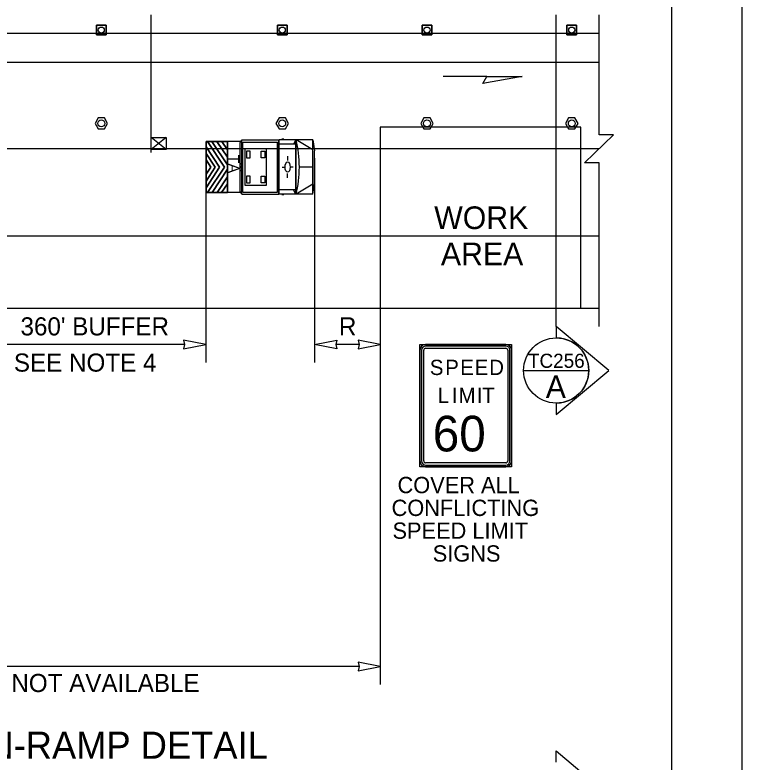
# Model space of a CAD drawing. Extents: x 99999 to 100116, y 99995 to 100013.
# Drawn here: x 100072.847 to 100076.062, y 100004.786 to 100008.087 of the extents above; entities that cross this region are included whole.
import ezdxf

# ---------------------------------------------------------------- set-up
doc = ezdxf.new("R2010")
doc.units = 0
for name, color, linetype in [('RD_MK_LineEdgeYellow', 7, 'Continuous'), ('RD_MK_LineLane', 7, 'Continuous'), ('SH_DE_DetailHeading2Text', 7, 'Continuous'), ('SH_GI_PlotLimits', 7, 'Continuous'), ('SH_GI_SectionCut', 7, 'Continuous'), ('SH_GI_SheetBorder', 7, 'Continuous'), ('TR_SN_ConstructionSigns', 7, 'Continuous'), ('TR_WZ_PortableSignMount5ftMinBlk-Wht', 7, 'Continuous'), ('TR_WZ_TallChanDevice', 7, 'Continuous'), ('TR_WZ_TrafficCone', 7, 'Continuous'), ('TR_WZ_TransportableAttenuator', 7, 'Continuous'), ('TR_WZ_WorkAreaLabel', 7, 'Continuous'), ('TR_WZ_WorkZoneDetails', 7, 'Continuous'), ('TR_WZ_WorkZoneTextCurrent', 7, 'Continuous')]:
    doc.layers.add(name, color=color, linetype=linetype)

msp = doc.modelspace()

# ---------------------------------------------------------------- linework, layer by layer
at = {"layer": 'RD_MK_LineEdgeYellow'}
for p, q in [((100068.195, 100007.8789), (100075.43, 100007.8789)), ((100072.7368, 100007.1109), (100075.43, 100007.1109))]:
    msp.add_line(p, q, dxfattribs=at)
at = {"layer": 'RD_MK_LineLane'}
msp.add_lwpolyline([(100075.43, 100007.4949), (100068.195, 100007.4949)], dxfattribs=at)
at = {"layer": 'SH_GI_PlotLimits'}
msp.add_lwpolyline([(100059.0625, 99999.6875), (100076.0625, 99999.6875), (100076.0625, 100010.6875), (100059.0625, 100010.6875)], close=True, dxfattribs=at)
at = {"layer": 'SH_GI_SectionCut'}
for p, q in [((100075.2407, 100006.7109), (100075.2407, 100008.0869)), ((100075.2407, 100006.7109), (100075.2407, 100006.66)), ((100075.4733, 100006.516), (100075.2407, 100006.7109)), ((100075.2407, 100006.3211), (100075.4733, 100006.516)), ((100075.2407, 100006.372), (100075.2407, 100006.3211)), ((100075.2407, 100004.7848), (100075.2407, 100004.8357)), ((100075.2407, 100004.8357), (100075.4733, 100004.6408))]:
    msp.add_line(p, q, dxfattribs=at)
msp.add_lwpolyline([(100075.0967, 100006.516), (100075.3847, 100006.516)], dxfattribs=at)
msp.add_circle((100075.2407, 100006.516), 0.144, dxfattribs=at)
msp.add_arc((100075.2407, 100006.516), 0.144, 269.9978, 90.0022, dxfattribs=at)
at = {"layer": 'SH_GI_SheetBorder'}
msp.add_line((100075.75, 100010.375), (100075.75, 100000), dxfattribs=at)
at = {"layer": 'TR_SN_ConstructionSigns'}
for p, q in [((100074.6633, 100006.6309), (100075.0177, 100006.6309)), ((100075.0177, 100006.6309), (100074.6633, 100006.6309)), ((100075.0177, 100006.6239), (100074.6633, 100006.6239)), ((100074.6633, 100006.614), (100075.0177, 100006.614)), ((100074.638, 100006.1162), (100074.638, 100006.6056)), ((100074.638, 100006.6056), (100074.638, 100006.1162)), ((100074.6451, 100006.6056), (100074.6451, 100006.1162)), ((100074.6549, 100006.1162), (100074.6549, 100006.6056)), ((100075.0261, 100006.6056), (100075.0261, 100006.1162)), ((100075.036, 100006.1162), (100075.036, 100006.6056)), ((100075.043, 100006.6056), (100075.043, 100006.1162)), ((100075.043, 100006.1162), (100075.043, 100006.6056)), ((100075.0177, 100006.1078), (100074.6633, 100006.1078)), ((100074.6633, 100006.0979), (100075.0177, 100006.0979)), ((100075.0177, 100006.0909), (100074.6633, 100006.0909)), ((100074.6633, 100006.0909), (100075.0177, 100006.0909))]:
    msp.add_line(p, q, dxfattribs=at)
msp.add_lwpolyline([(100074.638, 100006.6309), (100075.043, 100006.6309), (100075.043, 100006.0909), (100074.638, 100006.0909)], close=True, dxfattribs=at)
for centre, radius, start, end in [((100074.6633, 100006.6056), 0.0253, 90, 180), ((100074.6633, 100006.6056), 0.0253, 90, 180), ((100074.6633, 100006.6056), 0.0183, 90, 180), ((100074.6633, 100006.6056), 0.00844, 90, 180), ((100075.0177, 100006.6056), 0.0253, 0, 90), ((100075.0177, 100006.6056), 0.0253, 360, 90), ((100075.0177, 100006.6056), 0.0183, 0, 90), ((100075.0177, 100006.6056), 0.00844, 360, 90), ((100074.6633, 100006.1162), 0.0253, 180, 270), ((100074.6633, 100006.1162), 0.0253, 180, 270), ((100074.6633, 100006.1162), 0.0183, 180, 270), ((100074.6633, 100006.1162), 0.00844, 180, 270), ((100075.0177, 100006.1162), 0.0253, 270, 0), ((100075.0177, 100006.1162), 0.0183, 270, 360), ((100075.0177, 100006.1162), 0.00844, 270, 0), ((100075.0177, 100006.1162), 0.0253, 270, 0)]:
    msp.add_arc(centre, radius, start, end, dxfattribs=at)
at = {"layer": 'TR_WZ_PortableSignMount5ftMinBlk-Wht'}
for p, q in [((100073.45, 100007.4789), (100073.45, 100007.5589)), ((100073.5167, 100007.5449), (100073.45, 100007.4929)), ((100073.5167, 100007.4929), (100073.45, 100007.5449)), ((100073.4834, 100007.5189), (100073.4834, 100007.5189)), ((100073.4835, 100007.519), (100073.4835, 100007.519))]:
    msp.add_line(p, q, dxfattribs=at)
msp.add_lwpolyline([(100073.5167, 100007.5449), (100073.5167, 100007.4929), (100073.45, 100007.4929), (100073.45, 100007.5449)], close=True, dxfattribs=at)
at = {"layer": 'TR_WZ_TallChanDevice'}
for points in [[(100073.2433, 100007.6319), (100073.2155, 100007.6319), (100073.2017, 100007.6079), (100073.2155, 100007.5839), (100073.2433, 100007.5839), (100073.2571, 100007.6079)], [(100074.0433, 100007.6319), (100074.0155, 100007.6319), (100074.0017, 100007.6079), (100074.0155, 100007.5839), (100074.0433, 100007.5839), (100074.0571, 100007.6079)], [(100074.6833, 100007.6319), (100074.6555, 100007.6319), (100074.6417, 100007.6079), (100074.6555, 100007.5839), (100074.6833, 100007.5839), (100074.6971, 100007.6079)], [(100075.3233, 100007.6319), (100075.2955, 100007.6319), (100075.2817, 100007.6079), (100075.2955, 100007.5839), (100075.3233, 100007.5839), (100075.3371, 100007.6079)]]:
    msp.add_lwpolyline(points, close=True, dxfattribs=at)
for points in [[(100073.2433, 100007.6319), (100073.2155, 100007.6319), (100073.2017, 100007.6079), (100073.2155, 100007.5839), (100073.2433, 100007.5839), (100073.2571, 100007.6079), (100073.2433, 100007.6319)], [(100074.0433, 100007.6319), (100074.0155, 100007.6319), (100074.0017, 100007.6079), (100074.0155, 100007.5839), (100074.0433, 100007.5839), (100074.0571, 100007.6079), (100074.0433, 100007.6319)], [(100074.6833, 100007.6319), (100074.6555, 100007.6319), (100074.6417, 100007.6079), (100074.6555, 100007.5839), (100074.6833, 100007.5839), (100074.6971, 100007.6079), (100074.6833, 100007.6319)], [(100075.3233, 100007.6319), (100075.2955, 100007.6319), (100075.2817, 100007.6079), (100075.2955, 100007.5839), (100075.3233, 100007.5839), (100075.3371, 100007.6079), (100075.3233, 100007.6319)]]:
    msp.add_lwpolyline(points, dxfattribs=at)
for centre in [(100073.2294, 100007.6079), (100074.0294, 100007.6079), (100074.6694, 100007.6079), (100075.3094, 100007.6079)]:
    msp.add_circle(centre, 0.015, dxfattribs=at)
at = {"layer": 'TR_WZ_TrafficCone'}
for points in [[(100073.2081, 100008.0416), (100073.2507, 100008.0416), (100073.2507, 100007.9989), (100073.2081, 100007.9989), (100073.2081, 100008.0416)], [(100073.2081, 100007.9989), (100073.2507, 100007.9989), (100073.2507, 100008.0416), (100073.2081, 100008.0416), (100073.2081, 100007.9989)], [(100074.0081, 100008.0416), (100074.0507, 100008.0416), (100074.0507, 100007.9989), (100074.0081, 100007.9989), (100074.0081, 100008.0416)], [(100074.0081, 100007.9989), (100074.0507, 100007.9989), (100074.0507, 100008.0416), (100074.0081, 100008.0416), (100074.0081, 100007.9989)], [(100074.6481, 100008.0416), (100074.6907, 100008.0416), (100074.6907, 100007.9989), (100074.6481, 100007.9989), (100074.6481, 100008.0416)], [(100074.6481, 100007.9989), (100074.6907, 100007.9989), (100074.6907, 100008.0416), (100074.6481, 100008.0416), (100074.6481, 100007.9989)], [(100075.2881, 100008.0416), (100075.3307, 100008.0416), (100075.3307, 100007.9989), (100075.2881, 100007.9989), (100075.2881, 100008.0416)], [(100075.2881, 100007.9989), (100075.3307, 100007.9989), (100075.3307, 100008.0416), (100075.2881, 100008.0416), (100075.2881, 100007.9989)]]:
    msp.add_lwpolyline(points, dxfattribs=at)
for centre in [(100073.2294, 100008.0202), (100074.0294, 100008.0202), (100074.6694, 100008.0202), (100075.3094, 100008.0202)]:
    msp.add_circle(centre, 0.0133, dxfattribs=at)
at = {"layer": 'TR_WZ_TransportableAttenuator'}
for p, q in [((100073.8512, 100007.5349), (100074.0137, 100007.5349)), ((100073.8512, 100007.2949), (100073.8512, 100007.5349)), ((100074.0137, 100007.2949), (100074.0137, 100007.5349)), ((100074.0159, 100007.2949), (100074.0159, 100007.5349)), ((100074.1651, 100007.5349), (100074.0159, 100007.5349)), ((100074.0362, 100007.5383), (100074.0273, 100007.5383)), ((100074.0813, 100007.5163), (100074.0891, 100007.5349)), ((100074.0891, 100007.2949), (100074.0891, 100007.5349)), ((100074.0905, 100007.2949), (100074.0905, 100007.5349)), ((100074.1651, 100007.491), (100074.0905, 100007.5349)), ((100074.1651, 100007.2949), (100074.1651, 100007.5349)), ((100074.1651, 100007.5349), (100074.1724, 100007.4865)), ((100073.7525, 100007.414), (100073.6924, 100007.5046)), ((100073.6924, 100007.5046), (100073.6924, 100007.4751)), ((100073.6924, 100007.4751), (100073.6924, 100007.5046)), ((100073.6924, 100007.5046), (100073.7525, 100007.414)), ((100073.7186, 100007.5275), (100073.6986, 100007.5275)), ((100073.6986, 100007.5275), (100073.7735, 100007.4147)), ((100073.7735, 100007.4147), (100073.6986, 100007.5275)), ((100073.6986, 100007.5275), (100073.7186, 100007.5275)), ((100073.7868, 100007.4248), (100073.7186, 100007.5275)), ((100073.7186, 100007.5275), (100073.7868, 100007.4248)), ((100073.7622, 100007.5275), (100073.7406, 100007.5275)), ((100073.7406, 100007.5275), (100073.7868, 100007.458)), ((100073.7868, 100007.458), (100073.7406, 100007.5275)), ((100073.7406, 100007.5275), (100073.7622, 100007.5275)), ((100073.7868, 100007.4912), (100073.7622, 100007.5275)), ((100073.7622, 100007.5275), (100073.7868, 100007.4912)), ((100073.8512, 100007.5273), (100073.7868, 100007.5273)), ((100073.7868, 100007.5273), (100073.7868, 100007.302)), ((100073.8436, 100007.3062), (100073.8436, 100007.5237)), ((100073.8471, 100007.531), (100073.8506, 100007.531)), ((100073.8506, 100007.2989), (100073.8506, 100007.531)), ((100073.8512, 100007.3024), (100073.8512, 100007.5273)), ((100073.8558, 100007.3045), (100073.8558, 100007.5253)), ((100073.8558, 100007.5253), (100074.0091, 100007.5253)), ((100074.0091, 100007.3045), (100074.0091, 100007.5253)), ((100074.0891, 100007.5163), (100074.0159, 100007.5163)), ((100073.6924, 100007.4751), (100073.7332, 100007.4137)), ((100073.7332, 100007.4137), (100073.6924, 100007.4751)), ((100073.7868, 100007.458), (100073.7868, 100007.4912)), ((100073.7868, 100007.4912), (100073.7868, 100007.458)), ((100074.1724, 100007.3434), (100074.1724, 100007.4865)), ((100073.7133, 100007.4146), (100073.6924, 100007.446)), ((100073.6924, 100007.446), (100073.6924, 100007.3835)), ((100073.6924, 100007.446), (100073.7133, 100007.4146)), ((100073.6924, 100007.3835), (100073.6924, 100007.446)), ((100074.0533, 100007.4625), (100074.0533, 100007.4431)), ((100073.6924, 100007.3835), (100073.7133, 100007.4146)), ((100073.7133, 100007.4146), (100073.6924, 100007.3835)), ((100073.6924, 100007.3235), (100073.7525, 100007.414)), ((100073.7525, 100007.414), (100073.6924, 100007.3235)), ((100073.7332, 100007.4137), (100073.6924, 100007.3526)), ((100073.6924, 100007.3526), (100073.7332, 100007.4137)), ((100073.7735, 100007.4147), (100073.6986, 100007.302)), ((100073.6986, 100007.302), (100073.7735, 100007.4147)), ((100073.719, 100007.302), (100073.7868, 100007.4048)), ((100073.7868, 100007.4048), (100073.719, 100007.302)), ((100073.7868, 100007.4048), (100073.7868, 100007.4248)), ((100073.7868, 100007.4248), (100073.7868, 100007.4048)), ((100073.8436, 100007.4318), (100073.8506, 100007.4273)), ((100073.8436, 100007.398), (100073.8506, 100007.4025)), ((100073.8455, 100007.4149), (100073.8487, 100007.4149)), ((100073.8471, 100007.4116), (100073.8471, 100007.4183)), ((100074.0295, 100007.4148), (100074.0394, 100007.4148)), ((100074.0422, 100007.4153), (100074.0422, 100007.4153)), ((100074.0771, 100007.4148), (100074.0672, 100007.4148)), ((100074.1651, 100007.4149), (100074.1051, 100007.4149)), ((100073.7868, 100007.3715), (100073.7412, 100007.302)), ((100073.7412, 100007.302), (100073.7868, 100007.3715)), ((100073.7868, 100007.3402), (100073.7868, 100007.3715)), ((100073.7868, 100007.3715), (100073.7868, 100007.3402)), ((100074.0533, 100007.3674), (100074.0533, 100007.3868)), ((100073.6924, 100007.3526), (100073.6924, 100007.3235)), ((100073.6924, 100007.3235), (100073.6924, 100007.3526)), ((100073.7615, 100007.302), (100073.7868, 100007.3402)), ((100073.7868, 100007.3402), (100073.7615, 100007.302)), ((100074.1651, 100007.3389), (100074.0905, 100007.2949)), ((100074.1651, 100007.2949), (100074.1724, 100007.3434)), ((100073.8558, 100007.3045), (100074.0091, 100007.3045)), ((100074.0891, 100007.3135), (100074.0159, 100007.3135)), ((100074.0891, 100007.2949), (100074.0796, 100007.3135)), ((100073.6986, 100007.302), (100073.719, 100007.302)), ((100073.719, 100007.302), (100073.6986, 100007.302)), ((100073.7412, 100007.302), (100073.7615, 100007.302)), ((100073.7615, 100007.302), (100073.7412, 100007.302)), ((100073.8512, 100007.302), (100073.7868, 100007.302)), ((100073.8471, 100007.2989), (100073.8506, 100007.2989)), ((100073.8512, 100007.2949), (100074.0137, 100007.2949)), ((100074.1651, 100007.2949), (100074.0159, 100007.2949)), ((100074.0362, 100007.2915), (100074.0273, 100007.2915))]:
    msp.add_line(p, q, dxfattribs=at)
for points in [[(100073.7868, 100007.5275), (100073.6924, 100007.5275), (100073.6924, 100007.302), (100073.7868, 100007.302)], [(100073.8638, 100007.3349), (100073.9598, 100007.3349), (100073.9598, 100007.4949), (100073.8638, 100007.4949)], [(100073.8718, 100007.4549), (100073.8878, 100007.4549), (100073.8878, 100007.4849), (100073.8718, 100007.4849)], [(100073.9518, 100007.4549), (100073.9358, 100007.4549), (100073.9358, 100007.4849), (100073.9518, 100007.4849)], [(100073.8718, 100007.3449), (100073.8878, 100007.3449), (100073.8878, 100007.3749), (100073.8718, 100007.3749)], [(100073.9518, 100007.3449), (100073.9358, 100007.3449), (100073.9358, 100007.3749), (100073.9518, 100007.3749)]]:
    msp.add_lwpolyline(points, close=True, dxfattribs=at)
msp.add_lwpolyline([(100073.7868, 100007.302), (100073.6924, 100007.302), (100073.6924, 100007.5275), (100073.7868, 100007.5273)], dxfattribs=at)
for centre, major_axis, start_param, end_param in [((100073.9838, 100007.4149), (0, 0.2519), 4.215667, 5.208926), ((100073.8471, 100007.5237), (0, 0.00732), 0, 1.570796), ((100073.8471, 100007.3062), (0, -0.00732), 4.712389, 6.283185)]:
    msp.add_ellipse(centre, major_axis=major_axis, ratio=0.481608, start_param=start_param, end_param=end_param, dxfattribs=at)
for centre, major_axis in [((100074.0533, 100007.4149), (0, -0.0231)), ((100073.8471, 100007.4149), (0, -0.00338))]:
    msp.add_ellipse(centre, major_axis=major_axis, ratio=0.481608, dxfattribs=at)
at = {"layer": 'TR_WZ_WorkZoneDetails'}
for p, q in [((100073.45, 100007.5589), (100073.45, 100008.0869)), ((100068.195, 100008.0069), (100075.43, 100008.0069)), ((100074.9336, 100007.8149), (100074.7408, 100007.8149)), ((100073.6914, 100007.4607), (100073.6914, 100006.5509)), ((100074.1724, 100007.4548), (100074.1724, 100006.5509)), ((100072.7368, 100006.7909), (100075.43, 100006.7909)), ((100074.4628, 100006.7909), (100074.4628, 100005.1282)), ((100073.5977, 100006.6309), (100072.8006, 100006.6309)), ((100074.3691, 100006.6309), (100074.2662, 100006.6309)), ((100074.3691, 100006.6309), (100074.2662, 100006.6309)), ((100074.3691, 100005.2082), (100070.6962, 100005.2082))]:
    msp.add_line(p, q, dxfattribs=at)
msp.add_lwpolyline([(100075.43, 100006.7109), (100075.43, 100007.433), (100075.366, 100007.433), (100075.494, 100007.5569), (100075.43, 100007.5569), (100075.43, 100008.0869)], dxfattribs=at)
for points in [[(100075.0909, 100007.8149), (100074.9158, 100007.7841), (100074.9336, 100007.8149)], [(100074.4628, 100007.5909), (100074.4628, 100006.7909), (100075.35, 100006.7909), (100075.35, 100007.5909)], [(100073.6914, 100006.6309), (100073.5931, 100006.6502), (100073.5977, 100006.6309), (100073.5931, 100006.6116)], [(100074.1724, 100006.6309), (100074.2707, 100006.6502), (100074.2662, 100006.6309), (100074.2707, 100006.6116)], [(100074.4628, 100006.6309), (100074.3645, 100006.6502), (100074.3691, 100006.6309), (100074.3645, 100006.6116)], [(100074.4628, 100005.2082), (100074.3645, 100005.2275), (100074.3691, 100005.2082), (100074.3645, 100005.1889)]]:
    msp.add_lwpolyline(points, close=True, dxfattribs=at)

# ---------------------------------------------------------------- texts
at = {"layer": 'SH_DE_DetailHeading2Text'}
msp.add_text('OPEN RIGHT TAPERED ON-RAMP DETAIL', height=0.12, rotation=360, dxfattribs=at).set_placement((100070.7557, 100004.8003))
at = {"layer": 'SH_GI_SectionCut'}
msp.add_text('TC256', height=0.0625, dxfattribs=at).set_placement((100075.1158, 100006.5276))
msp.add_text('A', height=0.1, rotation=359.99, dxfattribs=at).set_placement((100075.1945, 100006.394))
at = {"layer": 'TR_SN_ConstructionSigns'}
for s, height, p in [('S', 0.0675, (100074.6819, 100006.4959)), ('P', 0.0675, (100074.7501, 100006.4959)), ('E', 0.0675, (100074.8162, 100006.4959)), ('E', 0.0675, (100074.8803, 100006.4959)), ('D', 0.0675, (100074.9445, 100006.4959)), ('L', 0.0675, (100074.717, 100006.3722)), ('I', 0.0675, (100074.7791, 100006.3722)), ('M', 0.0675, (100074.8088, 100006.3722)), ('I', 0.0675, (100074.8898, 100006.3722)), ('T', 0.0675, (100074.9134, 100006.3722)), ('60', 0.1575, (100074.6949, 100006.1584)), ('COVER ALL', 0.072, (100074.5392, 100005.9739)), ('CONFLICTING', 0.072, (100074.5128, 100005.8731)), ('SPEED LIMIT', 0.072, (100074.5168, 100005.7723)), ('SIGNS', 0.072, (100074.6947, 100005.6715))]:
    msp.add_text(s, height=height, dxfattribs=at).set_placement(p)
at = {"layer": 'TR_WZ_TransportableAttenuator'}
msp.add_text('TA', height=0.048, rotation=270, dxfattribs=at).set_placement((100073.7912, 100007.4698))
at = {"layer": 'TR_WZ_WorkAreaLabel'}
for s, p in [('WORK', (100074.7013, 100007.1409)), ('AREA', (100074.7309, 100006.9809))]:
    msp.add_text(s, height=0.1, dxfattribs=at).set_placement(p)
at = {"layer": 'TR_WZ_WorkZoneTextCurrent'}
for s, p in [("360' BUFFER", (100072.8721, 100006.6709)), ('R', (100074.28, 100006.6709)), ('R', (100074.28, 100006.6709)), ('SEE NOTE 4', (100072.8429, 100006.5109)), ('CLOSE ON-RAMP IF DISTANCE IS NOT AVAILABLE', (100071.0782, 100005.0953))]:
    msp.add_text(s, height=0.08, dxfattribs=at).set_placement(p)

doc.saveas('drawing.dxf')
